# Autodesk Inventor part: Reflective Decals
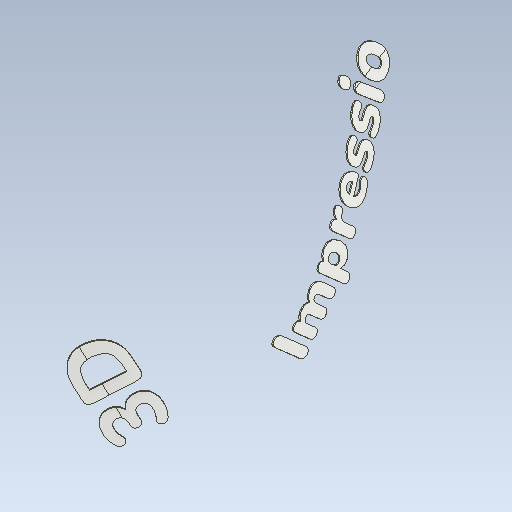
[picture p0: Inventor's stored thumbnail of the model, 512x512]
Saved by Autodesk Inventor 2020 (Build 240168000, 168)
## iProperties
Created: 2021-10
Part Number: Reflective Decals
Material: Steel
Document SubType Name: Modeling
Designer: bruno
Density: 7.85 g/cm^3
Appearance: Par défaut
Author: bruno
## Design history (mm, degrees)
feature "Body36"
feature "Body8"
feature "Body26"
feature "Body27"
feature "Body29"
feature "Body31"
feature "Body32"
feature "Body30"
feature "Body38"
feature "Body39"
feature "Body28"
feature "Body40"
node "Solide1"
node "Solide2"
node "Solide3"
node "Solide4"
node "Solide5"
node "Solide6"
node "Solide7"
node "Solide8"
node "Solide9"
node "Solide10"
node "Solide11"
node "Solide12"
